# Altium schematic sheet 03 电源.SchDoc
size 297 x 209 mm
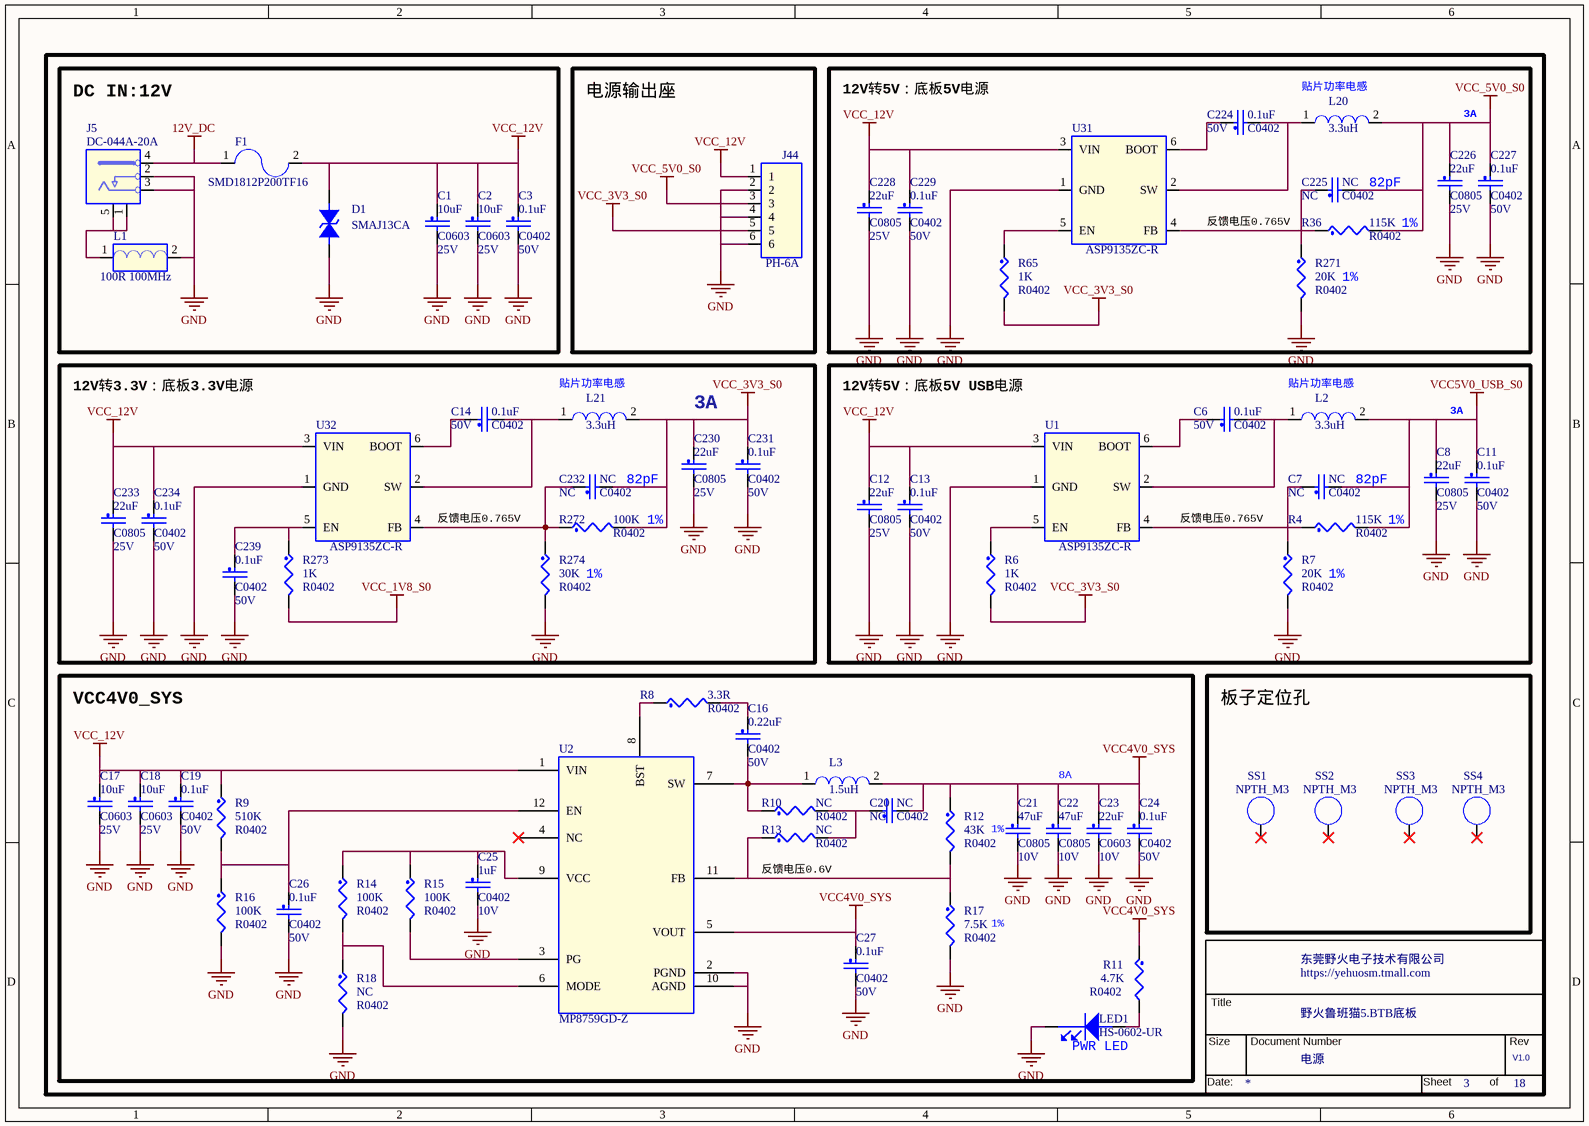
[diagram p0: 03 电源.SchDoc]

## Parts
*  Doc: 电源  RevCode: V1.0  Title: 野火鲁班猫5.BTB底板  OrgName: 东莞野火电子技术有限公司  Page Number: 3  Page Count: 18  (hidden comment: TitleBlock_YHSCH)  (graphical)
C1  10uF  Voltage: 25V  [C0603]
C2  10uF  Voltage: 25V  [C0603]
C3  0.1uF  Voltage: 50V  [C0402]
C6  0.1uF  Voltage: 50V  [C0402]
C7  NC  [C0402]
C8  22uF  Voltage: 25V  [C0805]
C11  0.1uF  Voltage: 50V  [C0402]
C12  22uF  Voltage: 25V  [C0805]
C13  0.1uF  Voltage: 50V  [C0402]
C14  0.1uF  Voltage: 50V  [C0402]
C16  0.22uF  Voltage: 50V  [C0402]
C17  10uF  Voltage: 25V  [C0603]
C18  10uF  Voltage: 25V  [C0603]
C19  0.1uF  Voltage: 50V  [C0402]
C20  NC  [C0402]
C21  47uF  Voltage: 10V  [C0805]
C22  47uF  Voltage: 10V  [C0805]
C23  22uF  Voltage: 10V  [C0603]
C24  0.1uF  Voltage: 50V  [C0402]
C25  1uF  Voltage: 10V  [C0402]
C26  0.1uF  Voltage: 50V  [C0402]
C27  0.1uF  Voltage: 50V  [C0402]
C224  0.1uF  Voltage: 50V  [C0402]
C225  NC  [C0402]
C226  22uF  Voltage: 25V  [C0805]
C227  0.1uF  Voltage: 50V  [C0402]
C228  22uF  Voltage: 25V  [C0805]
C229  0.1uF  Voltage: 50V  [C0402]
C230  22uF  Voltage: 25V  [C0805]
C231  0.1uF  Voltage: 50V  [C0402]
C232  NC  [C0402]
C233  22uF  Voltage: 25V  [C0805]
C234  0.1uF  Voltage: 50V  [C0402]
C239  0.1uF  Voltage: 50V  [C0402]
D1  SMAJ13CA  [D0603/SMD]
F1  SMD1812P200TF16  [F1812]
J5  DC-044A-20A  [dc_in_th_3p_10r1x11r6]
J44  PH-6A  [PH-1X6-2P0]
L1  100R 100MHz  [L0603]
L2  3.3uH  [l4520]
L3  1.5uH  [L0518]
L20  3.3uH  [l4520]
L21  3.3uH  [l4520]
LED1  HS-0602-UR  [led_hs_0602_ur]
R4  115K  [R0402]
R6  1K  [R0402]
R7  20K  [R0402]
R8  3.3R  [R0402]
R9  510K  [R0402]
R10  NC  [R0402]
R11  4.7K  [R0402]
R12  43K  [R0402]
R13  NC  [R0402]
R14  100K  [R0402]
R15  100K  [R0402]
R16  100K  [R0402]
R17  7.5K  [R0402]
R18  NC  [R0402]
R36  115K  [R0402]
R65  1K  [R0402]
R271  20K  [R0402]
R272  100K  [R0402]
R273  1K  [R0402]
R274  30K  [R0402]
SS1  NPTH_M3  [NPTH_M3]
SS2  NPTH_M3  [NPTH_M3]
SS3  NPTH_M3  [NPTH_M3]
SS4  NPTH_M3  [NPTH_M3]
U1  ASP9135ZC-R  [SOT23_6]
U2  MP8759GD-Z  [QFN12-2R00X3R00]
U31  ASP9135ZC-R  [SOT23_6]
U32  ASP9135ZC-R  [SOT23_6]

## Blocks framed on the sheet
DC IN:12V: C1-C3 D1 F1 J5 L1
电源输出座: J44
12V转5V：底板5V电源: C224-C229 L20 R36 R65 R271 U31
3A: C14 C230-C234 C239 L21 R272-R274 U32
12V转5V：底板5V USB电源: C6-C8 C11-C13 L2 R4 R6 R7 U1
VCC4V0_SYS: C16-C27 L3 LED1 R8-R18 U2
板子定位孔: SS1-SS4

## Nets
12V_DC: F1.1 J5.4
GND: C1.2 C2.2 C3.2 C8.2 C11.2 C12.2 C13.2 C17.2 C18.2 C19.2 C21.2 C22.2 C23.2 C24.2 C25.2 C26.2 C27.2 C226.2 C227.2 C228.2 C229.2 C230.2 C231.2 C233.2 C234.2 C239.2 D1.1 J5.2 J5.3 J44.2 J44.4 J44.6 L1.2 LED1.1(CATHODE) R7.2 R16.2 R17.2 R18.2 R271.2 R274.2 U1.1(GND) U2.2(PGND) U2.10(AGND) U31.1(GND) U32.1(GND)
VCC4V0_SYS: C20.2 C21.1 C22.1 C23.1 C24.1 C27.1 L3.2 R11.1 R12.1 U2.5(VOUT)
VCC5V0_USB_S0: C7.2 C8.1 C11.1 L2.2 R4.2
VCC_1V8_S0: R273.2
VCC_3V3_S0: C230.1 C231.1 C232.2 J44.5 L21.2 R6.2 R65.2 R272.2
VCC_5V0_S0: C225.2 C226.1 C227.1 J44.3 L20.2 R36.2
VCC_12V: C1.1 C2.1 C3.1 C12.1 C13.1 C17.1 C18.1 C19.1 C228.1 C229.1 C233.1 C234.1 D1.2 F1.2 J44.1 R9.1 U1.3(VIN) U2.1(VIN) U31.3(VIN) U32.3(VIN)
NetC6_1: C6.1 U1.6(BOOT)
NetC6_2: C6.2 L2.1 U1.2(SW)
NetC7_1: C7.1 R4.1 R7.1 U1.4(FB)
NetC14_1: C14.1 U32.6(BOOT)
NetC14_2: C14.2 L21.1 U32.2(SW)
NetC16_1: C16.1 R8.2
NetC16_2: C16.2 L3.1 R10.1 U2.7(SW)
NetC20_1: C20.1 R10.2 R13.2
NetC25_1: C25.1 R14.1 R15.1 U2.9(VCC)
NetC26_1: C26.1 R9.2 R16.1 U2.12(EN)
NetC224_1: C224.1 U31.6(BOOT)
NetC224_2: C224.2 L20.1 U31.2(SW)
NetC225_1: C225.1 R36.1 R271.1 U31.4(FB)
NetC232_1: C232.1 R272.1 R274.1 U32.4(FB)
NetC239_1: C239.1 R273.1 U32.5(EN)
NetJ5_1: J5.1 J5.5 L1.1
NetLED1_2: LED1.2(ANODE) R11.2
NetR6_1: R6.1 U1.5(EN)
NetR8_1: R8.1 U2.8(BST)
NetR12_2: R12.2 R13.1 R17.1 U2.11(FB)
NetR14_2: R14.2 R18.1 U2.6(MODE)
NetR15_2: R15.2 U2.3(PG)
NetR65_1: R65.1 U31.5(EN)

Not connected (* = marked no-connect by the designer): SS1 1(NC_1)*; SS2 1(NC_1)*; SS3 1(NC_1)*; SS4 1(NC_1)*; U2 4(NC)*

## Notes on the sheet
- (near L20) 贴片功率电感
- 3A
- 82pF
- 反馈电压0.765V
- 1%
- 12V转3.3V：底板3.3V电源
- (near L21) 贴片功率电感
- (near L2) 贴片功率电感
- (near U32) 反馈电压0.765V
- 8A
- (near R13) 反馈电压0.6V
- (near C21) 1%
- (near R17) 1%
- (near LED1) PWR LED

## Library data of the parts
* = TitleBlock_YHSCH: Cage Code: 1
C1 C2 C17 C18 = CAP_NP: CLASS: DISCRETE; 生命周期: 量产; 价格: 0.109811; 规格书: 三星电容.pdf; 类别: 贴片电容0603; 品牌: 三星; 条码: EBF29060171; 规格编号: CL10A106MA8NRNC; 规格: 贴片电容10uF 20% 25V X5R 0603
C3 C24 C27 C229 = CAP_NP: CLASS: DISCRETE; 规格: 贴片电容0.1uF 10% 50V X5R 0402; 规格编号: 0402X104K500NT; 条码: EBF29060118; 品牌: 风华; 类别: 贴片电容0402; 规格书: 风华电容.pdf; 价格: 0.029826; 生命周期: 量产
C6 C11 C13 C14 C19 C26 C224 C227 C231 C234 C239 = CAP_NP: CLASS: DISCRETE; 生命周期: 量产; 价格: 0.029826; 规格书: 风华电容.pdf; 类别: 贴片电容0402; 品牌: 风华; 条码: EBF29060118; 规格编号: 0402X104K500NT; 规格: 贴片电容0.1uF 10% 50V X5R 0402
C7 C20 C225 C232 = CAP_NP: CLASS: DISCRETE; 规格: 贴片电容NC 预留; 条码: EBF29060149; 类别: 贴片电容0402
C8 C12 C226 C230 C233 = CAP_NP: CLASS: DISCRETE; 规格: 贴片电容22uF 20% 25V X5R 0805; 规格编号: 0805X226M250NT; 条码: EBF29060173; 品牌: 风华; 类别: 贴片电容0805; 规格书: 风华电容.pdf; 价格: 0.285631; 生命周期: 量产
C16 = CAP_NP: CLASS: DISCRETE; 生命周期: 量产; 价格: 0.074942; 规格书: 太诱-贴片电容.pdf; 类别: 贴片电容0402; 品牌: 太诱; 条码: EBF29060266; 规格编号: UMK105BJ224MV-F; 规格: 贴片电容0.22uF 20% 50V X5R 0402
C21 = CAP_NP: CLASS: DISCRETE; 规格: 贴片电容47uF 20% 10V X5R 0805; 规格编号: 0805X476M100NT; 条码: EBF29060212; 品牌: 风华; 类别: 贴片电容0805; 规格书: 风华电容.pdf; 价格: 0.368494; 生命周期: 量产
C22 = CAP_NP: CLASS: DISCRETE; 生命周期: 量产; 价格: 0.368494; 规格书: 风华电容.pdf; 类别: 贴片电容0805; 品牌: 风华; 条码: EBF29060212; 规格编号: 0805X476M100NT; 规格: 贴片电容47uF 20% 10V X5R 0805
C23 = CAP_NP: CLASS: DISCRETE; 生命周期: 量产; 价格: 0.078818; 规格书: 三星电容.pdf; 类别: 贴片电容0603; 品牌: 三星; 条码: EBF29060163; 规格编号: CL10A226MP8NUNE; 规格: 贴片电容22uF 20% 10V X5R 0603
C25 = CAP_NP: CLASS: DISCRETE; 规格: 贴片电容1uF 10% 10V X5R 0402; 规格编号: 0402X105K100NT; 条码: EBF29060121; 品牌: 风华; 类别: 贴片电容0402; 规格书: 风华电容.pdf; 价格: 0.01191; 生命周期: 量产
C228 = CAP_NP: CLASS: DISCRETE; 生命周期: 量产; 价格: 0.285631; 规格书: 风华电容.pdf; 类别: 贴片电容0805; 品牌: 风华; 条码: EBF29060173; 规格编号: 0805X226M250NT; 规格: 贴片电容22uF 20% 25V X5R 0805
D1 = DIODE BI-DIR TRIG: 规格: TVS二极管 箝位电压21.5V 击穿电压14.4V 反向关断电压13V; 条码: EBF29140049; 品牌: 伯恩半导体; 类别: 贴片TVS; PCB Footprint: SMA_CA; 规格书: 伯恩半导体-SMAJ13CA.pdf; 价格: 0.181964; 生命周期: 量产
F1 = FUSE: 规格: 自恢复保险丝 最大电压46V 最大电流100A 保持电流2A 跳闸电流4A; 条码: EBF29270006; 品牌: 瑞隆源; 类别: 自恢复保险丝; 规格书: 瑞隆源-自恢复保险丝.pdf; 价格: 0.385618; 生命周期: 量产
J5 = DC-044A-20A: 生命周期: 量产; 规格书: DC插座_内径_2MM外径_5.9MM.pdf; 类别: DC电源座; 条码: EBF29040093; 规格编号: DC-044A-20A DC; 规格: DC-044A-20A DC插座
J44 = 1X6PIN: 规格: 直针PH2.0-6P 间距2.0MM 拔插式 接插件; 条码: EBF29020026; 品牌: 博穆精密; 类别: PH连接器; 规格书: 博穆精密_PH2.0-A.pdf; 价格: 0.0228; 生命周期: 量产
L1 = BEAD: CLASS: DISCRETE; 规格: 磁珠100Ω @100MHz 额定电流3A 直流电阻30mΩ; 规格编号: UPZ1608E101-3R0TF; 条码: EBF29050038; 品牌: 顺络; 类别: 贴片磁珠0603; 规格书: 顺络-磁珠.pdf; 价格: 0.021567; 生命周期: 量产
L2 = IND: CLASS: DISCRETE; 价格: 1.5992; 规格编号: TMPC0402HP-3R3MG-Z02; 规格: 贴片电感3.3uH ±20% 3A 直流电阻69mΩ; 条码: EBF29050040; 品牌: 台庆; 类别: 贴片电感0402; 规格书: 台庆-功率电感.pdf; 生命周期: 量产
L3 = IND: CLASS: DISCRETE; 生命周期: 量产; 价格: 0.525895; 规格书: 长江微电_FXL0518-1R5-M.pdf; 类别: 贴片电感SMD; 品牌: 长江微电; 条码: EBFCIS221116170516; 规格编号: FXL0518-1R5-M; 规格: 贴片电感1.5uH ±20% 7.5A 直流电阻25mΩ
L20 = IND: CLASS: DISCRETE; 价格: 1.5992; 规格编号: TMPC0402HP-3R3MG-Z02; 生命周期: 量产; 规格书: 台庆-功率电感.pdf; 类别: 贴片电感0402; 品牌: 台庆; 条码: EBF29050040; 规格: 贴片电感3.3uH ±20% 3A 直流电阻69mΩ
L21 = IND: CLASS: DISCRETE; 规格: 贴片电感3.3uH ±20% 3A 直流电阻69mΩ; 条码: EBF29050040; 品牌: 台庆; 类别: 贴片电感0402; 规格书: 台庆-功率电感.pdf; 生命周期: 量产; 规格编号: TMPC0402HP-3R3MG-Z02; 价格: 1.5992
LED1 = LED: 生命周期: 量产; 规格书: HS-0602-UR.pdf; 类别: 侧贴发光LED; 品牌: 鸿之森; 条码: EBF29140054; 规格: 侧贴0602LED 红色
R4 R36 = RES: CLASS: DISCRETE; 生命周期: 量产; 价格: 0.006087; 规格书: YAGEO国巨厚膜无铅电阻.pdf; 类别: 贴片电阻0402; 品牌: 国巨; 条码: EBF29070290; 规格编号: AC0402FR-07115KL; 规格: 贴片电阻115K 1% 1/16W 0402
R6 = RES: CLASS: DISCRETE; 规格: 贴片电阻1K 1% 1/16W 0402; 规格编号: RI0402L1001FT; 条码: EBF29070050; 品牌: 合科泰; 类别: 贴片电阻0402; 规格书: 合科泰-RI系列电阻.pdf; 生命周期: 量产
R7 R271 = RES: CLASS: DISCRETE; 生命周期: 量产; 价格: 0.002473; 规格书: 厚声-无铅厚膜电阻.pdf; 类别: 贴片电阻0402; 品牌: 厚声; 条码: EBF29070223; 规格编号: 0402WGF2002TCE; 规格: 贴片电阻20K 1% 1/16W 0402
R8 = RES: CLASS: DISCRETE; 规格: 贴片电阻3.3R 1% 1/16W 0402; 规格编号: 0402WGF330KTCE; 条码: EBFCIS221116113428; 品牌: 厚声; 类别: 贴片电阻0402; 规格书: 厚声-无铅厚膜电阻.pdf; 价格: 0.003117; 生命周期: 量产
R9 = RES: CLASS: DISCRETE; 规格: 贴片电阻510K 1% 1/16W 0402; 规格编号: RI0603L5103FT; 条码: EBF29070241; 品牌: 合科泰; 类别: 贴片电阻0402; 规格书: 合科泰-RI系列电阻.pdf; 生命周期: 量产
R10 R13 = RES: CLASS: DISCRETE; 类别: 贴片电阻0402; 条码: EBF29070087; 规格: 贴片电阻NC 预留
R11 = RES: CLASS: DISCRETE; 规格: 贴片电阻4.7K 1% 1/16W 0402; 规格编号: RI0402L4701FT; 条码: EBF29070047; 品牌: 合科泰; 类别: 贴片电阻0402; 规格书: 合科泰-RI系列电阻.pdf; 生命周期: 量产
R12 = RES: CLASS: DISCRETE; 规格: 贴片电阻43K 1% 1/16W 0402; 规格编号: AC0402FR-0743KL; 条码: EBF29070011; 品牌: 国巨; 类别: 贴片电阻0402; 规格书: YAGEO国巨厚膜无铅电阻.pdf; 价格: 0.00683; 生命周期: 量产
R14 = RES: CLASS: DISCRETE; 生命周期: 量产; 规格书: 合科泰-RI系列电阻.pdf; 类别: 贴片电阻0402; 品牌: 合科泰; 条码: EBF29070054; 规格编号: RI0402L1003FT; 规格: 贴片电阻100K 1% 1/16W 0402
R15 R16 R272 = RES: CLASS: DISCRETE; 规格: 贴片电阻100K 1% 1/16W 0402; 规格编号: RI0402L1003FT; 条码: EBF29070054; 品牌: 合科泰; 类别: 贴片电阻0402; 规格书: 合科泰-RI系列电阻.pdf; 生命周期: 量产
R17 = RES: CLASS: DISCRETE; 规格: 贴片电阻7.5K 1% 1/16W 0402; 规格编号: 0402WGF7501TCE; 条码: EBFCIS221112140245; 品牌: 厚声; 类别: 贴片电阻0402; 规格书: 厚声-无铅厚膜电阻.pdf; 价格: 0.001521; 生命周期: 量产
R18 = RES: CLASS: DISCRETE; 规格: 贴片电阻NC 预留; 条码: EBF29070087; 类别: 贴片电阻0402
R65 R273 = RES: CLASS: DISCRETE; 生命周期: 量产; 规格书: 合科泰-RI系列电阻.pdf; 类别: 贴片电阻0402; 品牌: 合科泰; 条码: EBF29070050; 规格编号: RI0402L1001FT; 规格: 贴片电阻1K 1% 1/16W 0402
R274 = RES: CLASS: DISCRETE; 规格: 贴片电阻30K 1% 1/16W 0402; 规格编号: RI0402L3002FT; 条码: EBF29070048; 品牌: 合科泰; 类别: 贴片电阻0402; 规格书: 合科泰-RI系列电阻.pdf; 生命周期: 量产
SS1 = SPACER: CLASS: IC; 生命周期: 量产; 类别: M3螺丝孔; 品牌: 野火; 条码: EBFCIS220926102704; 规格编号: M3螺丝孔_无铜
SS2-SS4 = SPACER: CLASS: IC; 规格编号: M3螺丝孔_无铜; 条码: EBFCIS220926102704; 品牌: 野火; 类别: M3螺丝孔; 生命周期: 量产
U1 = TP6327GS6: 规格: DC-DC电源芯片 可输出电流 3A 开关工作频率 600kHz 输出类型 ADJ 输入电压范围：4V-18V; 条码: EBFCIS240710113940; 品牌: 安森德; 类别: 电源管理-DCDC; 规格书: 安森德_ASP9135ZC-R.pdf; 生命周期: 量产; 备注: RK3566金手指与BTB底板替换物料
U2 = MP8759GD-Z: 生命周期: 量产; 价格: 3.2; 规格书: MPS_MP8759GD-Z.pdf; 类别: 电源管理-DCDC; 品牌: MPS; 条码: EBFCIS221112174800; 规格: DC-DC电源芯片 输入：4.5V-26V 电流：8A 频率: 固定700KHz频率  FB：0.6V
U31 U32 = TP6327GS6: 备注: RK3566金手指与BTB底板替换物料; 生命周期: 量产; 规格书: 安森德_ASP9135ZC-R.pdf; 类别: 电源管理-DCDC; 品牌: 安森德; 条码: EBFCIS240710113940; 规格: DC-DC电源芯片 可输出电流 3A 开关工作频率 600kHz 输出类型 ADJ 输入电压范围：4V-18V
